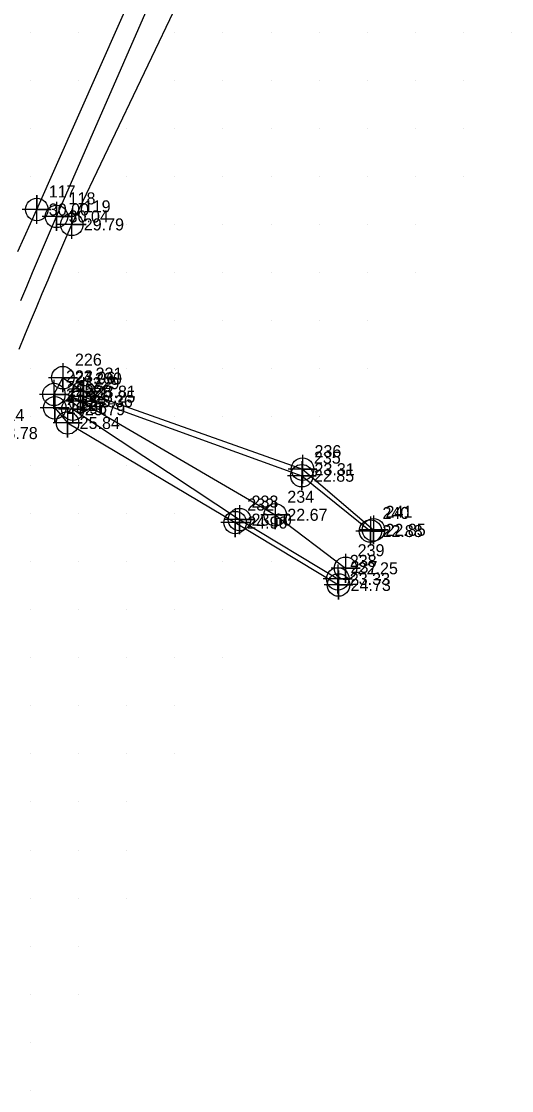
# Model space of a CAD drawing. Extents: x 2204340 to 2204783, y 268170 to 268760.
# Drawn here: x 2204478.1 to 2204580, y 268180 to 268402.2 of the extents above; entities that cross this region are included whole.
import ezdxf

# ---------------------------------------------------------------- set-up
doc = ezdxf.new("R2010")
doc.units = 0
for name, color, linetype in [('Exist DTM Breakline', 7, 'Continuous'), ('Exist DTM Breakline Cogo Elevation', 7, 'Continuous'), ('Exist DTM Breakline Cogo Number', 7, 'Continuous'), ('Exist DTM Breakline Cogo Point CELL', 7, 'Continuous'), ('Exist DTM Crownline', 7, 'Continuous'), ('Exist DTM Crownline Cogo Elevation', 7, 'Continuous'), ('Exist DTM Crownline Cogo Number', 7, 'Continuous'), ('Exist DTM Crownline Cogo Point CELL', 7, 'Continuous'), ('Exist DTM QL2 LIDAR Elevation Point', 7, 'Continuous'), ('Exist Roads Soil', 7, 'Continuous'), ('Exist Roads Soil Cogo Elevation', 7, 'Continuous'), ('Exist Roads Soil Cogo Number', 7, 'Continuous'), ('Exist Roads Soil Cogo Point CELL', 7, 'Continuous')]:
    doc.layers.add(name, color=color, linetype=linetype)

msp = doc.modelspace()

# ---------------------------------------------------------------- linework, layer by layer
at = {"layer": 'Exist DTM Breakline'}
for points in [[(2204484.89, 268324.71), (2204486.76, 268328.17), (2204491.04, 268325.27), (2204536.53, 268309.15), (2204551.28, 268296.55)], [(2204484.89, 268324.71), (2204485.05, 268321.9), (2204487.73, 268318.76), (2204522.56, 268298.06), (2204544.03, 268285.09)], [(2204490.92, 268324.24), (2204536.41, 268307.8), (2204550.65, 268296.3)], [(2204490.41, 268323.29), (2204530.88, 268299.68), (2204545.5, 268288.55)], [(2204488.81, 268321.62), (2204523.45, 268298.67), (2204543.87, 268286.35)]]:
    msp.add_lwpolyline(points, dxfattribs=at)
at = {"layer": 'Exist DTM Breakline Cogo Point CELL'}
for points in [[(2204486.75, 268331.17), (2204486.75, 268325.17), (2204486.75, 268328.17), (2204489.75, 268328.17), (2204483.75, 268328.17)], [(2204484.89, 268327.7), (2204484.89, 268321.7), (2204484.89, 268324.7), (2204487.89, 268324.7), (2204481.89, 268324.7)], [(2204484.89, 268327.7), (2204484.89, 268321.7), (2204484.89, 268324.7), (2204487.89, 268324.7), (2204481.89, 268324.7)], [(2204490.41, 268326.29), (2204490.41, 268320.29), (2204490.41, 268323.29), (2204493.41, 268323.29), (2204487.41, 268323.29)], [(2204490.92, 268327.24), (2204490.92, 268321.24), (2204490.92, 268324.24), (2204493.92, 268324.24), (2204487.92, 268324.24)], [(2204491.04, 268328.27), (2204491.04, 268322.27), (2204491.04, 268325.27), (2204494.04, 268325.27), (2204488.04, 268325.27)], [(2204485.05, 268324.9), (2204485.05, 268318.9), (2204485.05, 268321.9), (2204488.05, 268321.9), (2204482.05, 268321.9)], [(2204488.81, 268324.62), (2204488.81, 268318.62), (2204488.81, 268321.62), (2204491.81, 268321.62), (2204485.81, 268321.62)], [(2204487.73, 268321.76), (2204487.73, 268315.76), (2204487.73, 268318.76), (2204490.73, 268318.76), (2204484.73, 268318.76)], [(2204536.41, 268310.8), (2204536.41, 268304.8), (2204536.41, 268307.8), (2204539.41, 268307.8), (2204533.41, 268307.8)], [(2204536.53, 268312.15), (2204536.53, 268306.15), (2204536.53, 268309.15), (2204539.53, 268309.15), (2204533.53, 268309.15)], [(2204523.45, 268301.67), (2204523.45, 268295.67), (2204523.45, 268298.67), (2204526.45, 268298.67), (2204520.45, 268298.67)], [(2204530.88, 268302.68), (2204530.88, 268296.68), (2204530.88, 268299.68), (2204533.88, 268299.68), (2204527.88, 268299.68)], [(2204522.56, 268301.05), (2204522.56, 268295.05), (2204522.56, 268298.05), (2204525.56, 268298.05), (2204519.56, 268298.05)], [(2204551.28, 268299.55), (2204551.28, 268293.55), (2204551.28, 268296.55), (2204554.28, 268296.55), (2204548.28, 268296.55)], [(2204550.65, 268299.3), (2204550.65, 268293.3), (2204550.65, 268296.3), (2204553.65, 268296.3), (2204547.65, 268296.3)], [(2204545.5, 268291.55), (2204545.5, 268285.55), (2204545.5, 268288.55), (2204548.5, 268288.55), (2204542.5, 268288.55)], [(2204543.87, 268289.35), (2204543.87, 268283.35), (2204543.87, 268286.35), (2204546.87, 268286.35), (2204540.87, 268286.35)], [(2204544.03, 268288.09), (2204544.03, 268282.09), (2204544.03, 268285.09), (2204547.03, 268285.09), (2204541.03, 268285.09)]]:
    msp.add_lwpolyline(points, dxfattribs=at)
for centre in [(2204486.75, 268328.17), (2204484.89, 268324.7), (2204484.89, 268324.7), (2204490.92, 268324.24), (2204491.04, 268325.27), (2204485.05, 268321.9), (2204488.81, 268321.62), (2204490.41, 268323.29), (2204487.73, 268318.76), (2204536.53, 268309.15), (2204536.41, 268307.8), (2204530.88, 268299.68), (2204522.56, 268298.05), (2204523.45, 268298.67), (2204550.65, 268296.3), (2204551.28, 268296.55), (2204545.5, 268288.55), (2204543.87, 268286.35), (2204544.03, 268285.09)]:
    msp.add_circle(centre, 2.34, dxfattribs=at)
at = {"layer": 'Exist DTM Crownline'}
msp.add_lwpolyline([(2204478, 268344.19), (2204479.23, 268347.11), (2204480.46, 268350.03), (2204481.69, 268352.95), (2204482.93, 268355.87), (2204484.18, 268358.78), (2204485.43, 268361.69), (2204506.39, 268409.72)], dxfattribs=at)
at = {"layer": 'Exist DTM Crownline Cogo Point CELL'}
msp.add_lwpolyline([(2204485.43, 268364.69), (2204485.43, 268358.69), (2204485.43, 268361.69), (2204488.43, 268361.69), (2204482.43, 268361.69)], dxfattribs=at)
msp.add_circle((2204485.43, 268361.69), 2.34, dxfattribs=at)
at = {"layer": 'Exist DTM QL2 LIDAR Elevation Point'}
for p, q in [((2204480, 268400), (2204480, 268400)), ((2204490, 268400), (2204490, 268400)), ((2204510, 268400), (2204510, 268400)), ((2204520, 268400), (2204520, 268400)), ((2204530, 268400), (2204530, 268400)), ((2204540, 268400), (2204540, 268400)), ((2204550, 268400), (2204550, 268400)), ((2204560, 268400), (2204560, 268400)), ((2204570, 268400), (2204570, 268400)), ((2204580, 268400), (2204580, 268400)), ((2204480, 268390), (2204480, 268390)), ((2204490, 268390), (2204490, 268390)), ((2204510, 268390), (2204510, 268390)), ((2204520, 268390), (2204520, 268390)), ((2204530, 268390), (2204530, 268390)), ((2204540, 268390), (2204540, 268390)), ((2204550, 268390), (2204550, 268390)), ((2204560, 268390), (2204560, 268390)), ((2204570, 268390), (2204570, 268390)), ((2204480, 268380), (2204480, 268380)), ((2204500, 268380), (2204500, 268380)), ((2204510, 268380), (2204510, 268380)), ((2204520, 268380), (2204520, 268380)), ((2204530, 268380), (2204530, 268380)), ((2204540, 268380), (2204540, 268380)), ((2204550, 268380), (2204550, 268380)), ((2204560, 268380), (2204560, 268380)), ((2204570, 268380), (2204570, 268380)), ((2204480, 268370), (2204480, 268370)), ((2204500, 268370), (2204500, 268370)), ((2204510, 268370), (2204510, 268370)), ((2204520, 268370), (2204520, 268370)), ((2204530, 268370), (2204530, 268370)), ((2204540, 268370), (2204540, 268370)), ((2204550, 268370), (2204550, 268370)), ((2204560, 268370), (2204560, 268370)), ((2204570, 268370), (2204570, 268370)), ((2204500, 268360), (2204500, 268360)), ((2204510, 268360), (2204510, 268360)), ((2204520, 268360), (2204520, 268360)), ((2204530, 268360), (2204530, 268360)), ((2204540, 268360), (2204540, 268360)), ((2204550, 268360), (2204550, 268360)), ((2204560, 268360), (2204560, 268360)), ((2204490, 268350), (2204490, 268350)), ((2204500, 268350), (2204500, 268350)), ((2204510, 268350), (2204510, 268350)), ((2204520, 268350), (2204520, 268350)), ((2204530, 268350), (2204530, 268350)), ((2204540, 268350), (2204540, 268350)), ((2204550, 268350), (2204550, 268350)), ((2204560, 268350), (2204560, 268350)), ((2204490, 268340), (2204490, 268340)), ((2204500, 268340), (2204500, 268340)), ((2204510, 268340), (2204510, 268340)), ((2204520, 268340), (2204520, 268340)), ((2204530, 268340), (2204530, 268340)), ((2204540, 268340), (2204540, 268340)), ((2204550, 268340), (2204550, 268340)), ((2204480, 268330), (2204480, 268330)), ((2204490, 268330), (2204490, 268330)), ((2204500, 268330), (2204500, 268330)), ((2204510, 268330), (2204510, 268330)), ((2204520, 268330), (2204520, 268330)), ((2204530, 268330), (2204530, 268330)), ((2204540, 268330), (2204540, 268330)), ((2204550, 268330), (2204550, 268330)), ((2204480, 268320), (2204480, 268320)), ((2204510, 268320), (2204510, 268320)), ((2204520, 268320), (2204520, 268320)), ((2204530, 268320), (2204530, 268320)), ((2204540, 268320), (2204540, 268320)), ((2204480, 268310), (2204480, 268310)), ((2204490, 268310), (2204490, 268310)), ((2204500, 268310), (2204500, 268310)), ((2204540, 268310), (2204540, 268310)), ((2204480, 268300), (2204480, 268300)), ((2204490, 268300), (2204490, 268300)), ((2204500, 268300), (2204500, 268300)), ((2204510, 268300), (2204510, 268300)), ((2204480, 268290), (2204480, 268290)), ((2204490, 268290), (2204490, 268290)), ((2204500, 268290), (2204500, 268290)), ((2204510, 268290), (2204510, 268290)), ((2204520, 268290), (2204520, 268290)), ((2204530, 268290), (2204530, 268290)), ((2204480, 268280), (2204480, 268280)), ((2204490, 268280), (2204490, 268280)), ((2204500, 268280), (2204500, 268280)), ((2204510, 268280), (2204510, 268280)), ((2204520, 268280), (2204520, 268280)), ((2204480, 268270), (2204480, 268270)), ((2204490, 268270), (2204490, 268270)), ((2204500, 268270), (2204500, 268270)), ((2204510, 268270), (2204510, 268270)), ((2204520, 268270), (2204520, 268270)), ((2204480, 268260), (2204480, 268260)), ((2204490, 268260), (2204490, 268260)), ((2204500, 268260), (2204500, 268260)), ((2204510, 268260), (2204510, 268260)), ((2204480, 268250), (2204480, 268250)), ((2204490, 268250), (2204490, 268250)), ((2204500, 268250), (2204500, 268250)), ((2204510, 268250), (2204510, 268250)), ((2204480, 268240), (2204480, 268240)), ((2204490, 268240), (2204490, 268240)), ((2204500, 268240), (2204500, 268240)), ((2204480, 268230), (2204480, 268230)), ((2204490, 268230), (2204490, 268230)), ((2204500, 268230), (2204500, 268230)), ((2204480, 268220), (2204480, 268220)), ((2204490, 268220), (2204490, 268220)), ((2204500, 268220), (2204500, 268220)), ((2204480, 268210), (2204480, 268210)), ((2204490, 268210), (2204490, 268210)), ((2204480, 268200), (2204480, 268200)), ((2204490, 268200), (2204490, 268200)), ((2204480, 268190), (2204480, 268190)), ((2204480, 268180), (2204480, 268180))]:
    msp.add_line(p, q, dxfattribs=at)
at = {"layer": 'Exist Roads Soil'}
for points in [[(2204477.4, 268354.43), (2204478.69, 268357.33), (2204479.99, 268360.23), (2204481.31, 268363.12), (2204502.89, 268411.73)], [(2204477.65, 268334.08), (2204478.83, 268336.98), (2204480.03, 268339.87), (2204481.23, 268342.76), (2204482.44, 268345.64), (2204483.66, 268348.53), (2204484.88, 268351.41), (2204486.11, 268354.29), (2204487.34, 268357.16), (2204488.58, 268360.04), (2204511.26, 268407.44)]]:
    msp.add_lwpolyline(points, dxfattribs=at)
at = {"layer": 'Exist Roads Soil Cogo Point CELL'}
for points in [[(2204481.31, 268360.12), (2204481.31, 268366.12), (2204481.31, 268363.12), (2204484.31, 268363.12), (2204478.31, 268363.12)], [(2204488.58, 268357.03), (2204488.58, 268363.03), (2204488.58, 268360.03), (2204491.58, 268360.03), (2204485.58, 268360.03)]]:
    msp.add_lwpolyline(points, dxfattribs=at)
for centre in [(2204481.31, 268363.12), (2204488.58, 268360.03)]:
    msp.add_circle(centre, 2.34, dxfattribs=at)

# ---------------------------------------------------------------- texts
at = {"layer": 'Exist DTM Breakline Cogo Elevation'}
for s, p in [('27.06', (2204489.25, 268326.92)), ('23.81', (2204493.54, 268324.02)), ('27.63', (2204487.39, 268323.45)), ('27.63', (2204487.39, 268323.45)), ('23.36', (2204492.91, 268322.04)), ('23.25', (2204493.42, 268322.99)), ('26.96', (2204487.55, 268320.65)), ('23.79', (2204491.31, 268320.37)), ('25.84', (2204490.23, 268317.51)), ('22.85', (2204538.91, 268306.55)), ('23.31', (2204539.03, 268307.9)), ('23.60', (2204525.95, 268297.42)), ('22.67', (2204533.38, 268298.43)), ('24.90', (2204525.06, 268296.8)), ('22.88', (2204553.15, 268295.05)), ('22.85', (2204553.78, 268295.3)), ('22.25', (2204548, 268287.3)), ('23.33', (2204546.37, 268285.1)), ('24.73', (2204546.53, 268283.84))]:
    msp.add_text(s, height=2.5, dxfattribs=at).set_placement(p)
at = {"layer": 'Exist DTM Breakline Cogo Number'}
for s, p in [('226', (2204489.25, 268330.67)), ('223', (2204487.39, 268327.2)), ('224', (2204487.39, 268327.2)), ('229', (2204492.91, 268325.79)), ('230', (2204493.42, 268326.74)), ('231', (2204493.54, 268327.77)), ('225', (2204487.55, 268324.4)), ('228', (2204491.31, 268324.12)), ('227', (2204490.23, 268321.26)), ('235', (2204538.91, 268310.3)), ('236', (2204539.03, 268311.65)), ('234', (2204533.38, 268302.18)), ('232', (2204525.06, 268300.55)), ('233', (2204525.95, 268301.17)), ('240', (2204553.15, 268298.8)), ('241', (2204553.78, 268299.05)), ('239', (2204548, 268291.05)), ('238', (2204546.37, 268288.85)), ('237', (2204546.53, 268287.59))]:
    msp.add_text(s, height=2.5, dxfattribs=at).set_placement(p)
at = {"layer": 'Exist DTM Crownline Cogo Elevation'}
msp.add_text('30.04', height=2.5, dxfattribs=at).set_placement((2204487.93, 268360.44))
at = {"layer": 'Exist DTM Crownline Cogo Number'}
msp.add_text('118', height=2.5, dxfattribs=at).set_placement((2204487.93, 268364.19))
at = {"layer": 'Exist Roads Soil Cogo Elevation'}
for s, p in [('30.00', (2204483.81, 268361.87)), ('29.79', (2204491.08, 268358.78)), ('28.78', (2204473.15, 268315.41))]:
    msp.add_text(s, height=2.5, dxfattribs=at).set_placement(p)
at = {"layer": 'Exist Roads Soil Cogo Number'}
for s, p in [('117', (2204483.81, 268365.62)), ('119', (2204491.08, 268362.53)), ('114', (2204473.15, 268319.16))]:
    msp.add_text(s, height=2.5, dxfattribs=at).set_placement(p)

doc.saveas('drawing.dxf')
